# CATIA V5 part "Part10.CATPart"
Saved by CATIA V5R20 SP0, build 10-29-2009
Part number: 9CS081215
Revision: ANY
Definition: UNKNOWN
Nomenclature: 9CS081215
Source: Unknown
Bounding box of the stored display mesh (mm): x -5.85 to 5.85, y -7.5 to 7.5, z -6 to 6
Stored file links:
  C:\Users\Utente\Desktop\IO LAVORO\3D X SITO CF\CUMSA\3D files PW\pw081230\pw081230_injection\Part10.CATPart
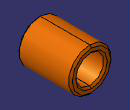
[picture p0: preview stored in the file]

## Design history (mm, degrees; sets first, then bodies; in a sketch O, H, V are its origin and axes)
Body1 "Revolución1" (main body)
  Solid1: solid without history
